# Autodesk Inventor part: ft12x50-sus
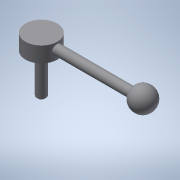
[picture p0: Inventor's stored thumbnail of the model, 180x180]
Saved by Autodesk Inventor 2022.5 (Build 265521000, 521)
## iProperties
Created: 2016-12
Part Number: ft12x50-sus
Material: 一般
Document SubType Name: Modeling
Designer: imaocorp
Density: 1 g/cm^3
Appearance: 既定
Author: imaocorp
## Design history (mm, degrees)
node "ft12x50-sus.x_t1"
node "ft12x50-sus"
node "Base1"
